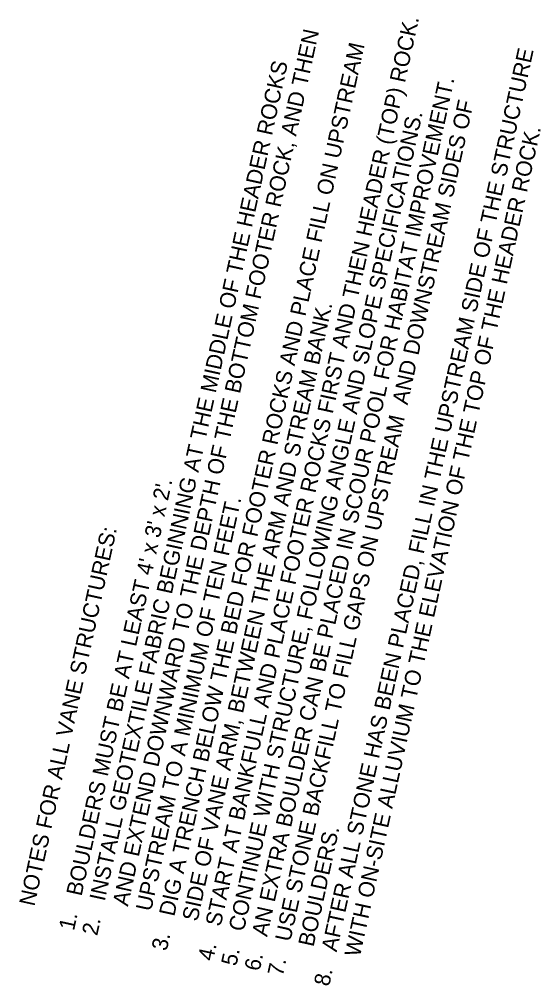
# Model space of a CAD drawing. Extents: x 2126110 to 2128246, y 1804858 to 1811658.
# Drawn here: x 2127587 to 2128246, y 1810240 to 1811461 of the extents above; entities that cross this region are included whole.
import ezdxf

# ---------------------------------------------------------------- set-up
doc = ezdxf.new("R2010")
doc.units = 0
doc.layers.add('1', color=7, linetype='Continuous')

msp = doc.modelspace()

# ---------------------------------------------------------------- texts
at = {"layer": '1'}
for s, rotation, p in [('4.   START AT BANKFULL AND PLACE FOOTER ROCKS FIRST AND THEN HEADER (TOP) ROCK.', 77.6736, (2127831.8, 1810270.7)), ('      AND EXTEND DOWNWARD TO THE DEPTH OF THE BOTTOM FOOTER ROCK, AND THEN', 77.6736, (2127714.6, 1810296.3)), ('3.   DIG A TRENCH BELOW THE BED FOR FOOTER ROCKS AND PLACE FILL ON UPSTREAM', 77.6736, (2127773.2, 1810283.5)), ('8.   AFTER ALL STONE HAS BEEN PLACED, FILL IN THE UPSTREAM SIDE OF THE STRUCTURE', 77.6736, (2127978.4, 1810238.7)), ('2.   INSTALL GEOTEXTILE FABRIC BEGINNING AT THE MIDDLE OF THE HEADER ROCKS', 77.6736, (2127685.3, 1810302.7)), ('6.   AN EXTRA BOULDER CAN BE PLACED IN SCOUR POOL FOR HABITAT IMPROVEMENT.', 77.6736, (2127890.5, 1810257.9)), ('7.   USE STONE BACKFILL TO FILL GAPS ON UPSTREAM  AND DOWNSTREAM SIDES OF', 77.6736, (2127919.8, 1810251.5)), ('5.   CONTINUE WITH STRUCTURE, FOLLOWING ANGLE AND SLOPE SPECIFICATIONS.', 77.6736, (2127861.1, 1810264.3)), ('      WITH ON-SITE ALLUVIUM TO THE ELEVATION OF THE TOP OF THE HEADER ROCK. ', 77.6736, (2128007.7, 1810232.3)), ('      SIDE OF VANE ARM, BETWEEN THE ARM AND STREAM BANK.', 77.6736, (2127802.5, 1810277.1)), ("1.   BOULDERS MUST BE AT LEAST 4' x 3' x 2'.", 77.6736, (2127656, 1810309.1)), ('      UPSTREAM TO A MINIMUM OF TEN FEET.', 77.6736, (2127743.9, 1810289.9)), ('NOTES FOR ALL VANE STRUCTURES:', 77.6735, (2127606, 1810339.9)), ('      BOULDERS.', 77.6736, (2127949.1, 1810245.1))]:
    msp.add_text(s, height=20, rotation=rotation, dxfattribs=at).set_placement(p)

doc.saveas('drawing.dxf')
